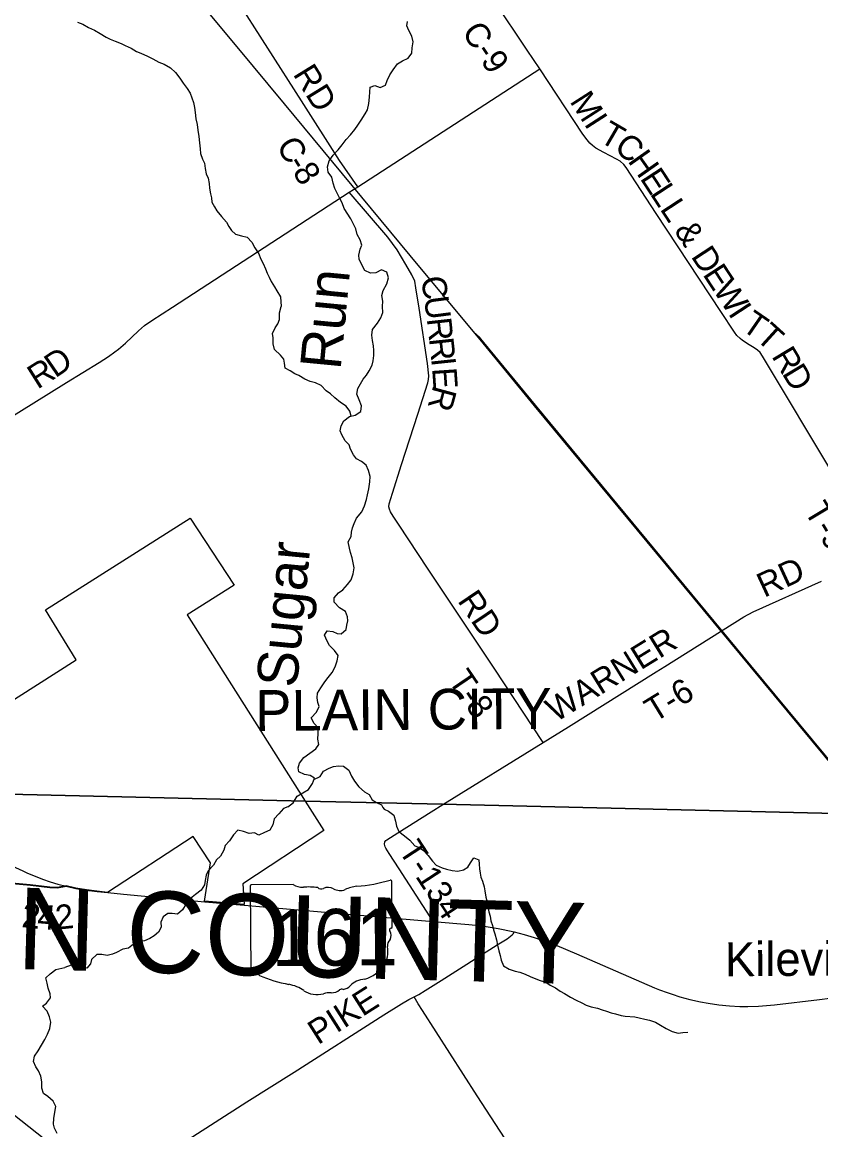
# Model space of a CAD drawing. Extents: x 114843 to 284848, y 317643 to 566895.
# Drawn here: x 135543 to 145352, y 436168 to 449771 of the extents above; entities that cross this region are included whole.
import ezdxf

# ---------------------------------------------------------------- set-up
doc = ezdxf.new("R2010")
doc.units = 0
for name, color, linetype in [('GM_X_Corporation', 7, 'Continuous'), ('GM_X_Corporation_Text', 7, 'Continuous'), ('GM_X_County', 7, 'Continuous'), ('GM_X_County_Road', 7, 'Continuous'), ('GM_X_County_Road_Text', 7, 'Continuous'), ('GM_X_County_Text', 7, 'Continuous'), ('GM_X_Minor_River', 7, 'Continuous'), ('GM_X_Minor_River_Text', 7, 'Continuous'), ('GM_X_Rail_Line', 7, 'Continuous'), ('GM_X_State_Location', 7, 'Continuous'), ('GM_X_State_Route', 7, 'Continuous'), ('GM_X_State_Shield', 7, 'Continuous'), ('GM_X_Township', 7, 'Continuous'), ('GM_X_Township_Road', 7, 'Continuous'), ('GM_X_Township_Road_Text', 7, 'Continuous'), ('GM_X_Unincorporated_Text', 7, 'Continuous')]:
    doc.layers.add(name, color=color, linetype=linetype)

msp = doc.modelspace()

# ---------------------------------------------------------------- linework, layer by layer
at = {"layer": 'GM_X_Corporation'}
msp.add_lwpolyline([(133681, 440330), (136208, 441939), (135832, 442553), (137605, 443679), (138147, 442857), (137568, 442491), (139019, 440206), (139249, 439843), (138253, 439188), (138269, 438934), (137783, 438976), (137857, 439448), (137645, 439771), (136593, 439084), (136462, 439098), (136332, 439114), (136203, 439137), (136085, 439163), (135978, 439145), (135882, 439149), (135643, 439176), (135285, 439209)], dxfattribs=at)
at = {"layer": 'GM_X_County'}
for points in [[(129305, 440437), (129824, 440418), (129960, 440416), (130670, 440400), (130865, 440395), (131182, 440388), (131530, 440380), (131888, 440371), (132489, 440358), (133681, 440330), (133879, 440325), (134855, 440302), (139019, 440206), (140707, 440166), (147260, 440014)], [(147260, 440014), (140707, 440166), (139019, 440206), (134855, 440302), (133879, 440325), (133681, 440330), (132489, 440358), (131888, 440371), (131530, 440380), (131182, 440388), (130865, 440395), (130670, 440400), (129960, 440416), (129824, 440418), (129305, 440437)]]:
    msp.add_lwpolyline(points, dxfattribs=at)
at = {"layer": 'GM_X_County_Road'}
for points in [[(141902, 449196), (141746, 449428), (141342, 450031), (141089, 450411), (140886, 450733), (140854, 450791), (140832, 450838), (140820, 450885), (140819, 450926), (140826, 450962), (140846, 450998), (140894, 451044), (141104, 451178), (141825, 451637), (141918, 451696), (142057, 451782), (142111, 451813), (142494, 451989), (142550, 452014), (142635, 452044), (142710, 452061), (142808, 452078), (145686, 452514)], [(139666, 447749), (139442, 448072), (138972, 448806), (137735, 450748), (137170, 451640), (136941, 451999)], [(134912, 444616), (136089, 445346), (136488, 445593), (136604, 445666), (136683, 445722), (136727, 445754), (136811, 445830), (136973, 445982), (137045, 446044), (137135, 446108), (137388, 446272), (139559, 447682), (139666, 447749), (141902, 449196)], [(134808, 439398), (135097, 439255), (135158, 439230), (135222, 439215), (135287, 439206), (135645, 439173), (135883, 439146), (135979, 439142), (136086, 439160)], [(140358, 437803), (140414, 437832), (140494, 437880), (140688, 438002), (141378, 438441), (141499, 438515), (141562, 438562), (141578, 438581), (141586, 438599)], [(136091, 434943), (136137, 435014), (136225, 435158), (136240, 435179), (136261, 435204), (136287, 435229), (136310, 435248), (136337, 435267), (136393, 435301), (136423, 435314), (136781, 435544), (137584, 436051), (138301, 436511), (138882, 436878), (139987, 437580), (140203, 437715), (140294, 437768), (140358, 437803)], [(146567, 428190), (146545, 428225), (146526, 428251), (146331, 428554), (145936, 429157), (145721, 429491), (145366, 430037), (145064, 430505), (144797, 430918), (144567, 431276), (144032, 432101), (143429, 433037), (143149, 433468), (142166, 434991), (142073, 435132), (141863, 435459), (141131, 436585), (140458, 437632), (140407, 437716), (140358, 437803)]]:
    msp.add_lwpolyline(points, dxfattribs=at)
at = {"layer": 'GM_X_Minor_River'}
for points in [[(136222, 449771), (136289, 449745), (136359, 449703), (136431, 449674), (136500, 449630), (136576, 449588), (136626, 449562), (136686, 449537), (136759, 449509), (136809, 449485), (136881, 449450), (136948, 449412), (137000, 449388), (137082, 449352), (137150, 449319), (137221, 449281), (137289, 449255), (137365, 449210), (137428, 449154), (137478, 449084), (137521, 449020), (137571, 448954), (137608, 448898), (137646, 448784), (137659, 448722), (137669, 448660), (137677, 448584), (137692, 448514), (137702, 448445), (137713, 448367), (137721, 448287), (137728, 448213), (137734, 448159), (137758, 448089), (137783, 448039), (137789, 447975), (137805, 447907), (137826, 447855), (137840, 447789), (137846, 447734), (137857, 447664), (137867, 447612), (137873, 447560), (137906, 447502), (137934, 447452), (137992, 447382), (138055, 447313), (138083, 447261), (138114, 447211), (138164, 447167), (138236, 447145), (138306, 447131), (138363, 447070), (138401, 447000), (138450, 446924), (138470, 446870), (138505, 446806), (138533, 446740), (138551, 446690), (138578, 446640), (138600, 446584), (138644, 446520), (138671, 446470), (138715, 446396), (138723, 446279)], [(139970, 446277), (139974, 446344), (139961, 446413), (139975, 446477), (140021, 446559), (140042, 446630), (140022, 446700), (139956, 446729), (139888, 446691), (139822, 446687), (139753, 446720), (139713, 446792), (139681, 446860), (139678, 446910), (139694, 446981), (139714, 447031), (139695, 447097), (139659, 447165), (139640, 447233), (139610, 447297), (139580, 447355), (139499, 447483), (139474, 447551), (139442, 447615), (139408, 447677), (139385, 447729), (139361, 447795), (139345, 447865), (139302, 447927), (139294, 447995), (139313, 448069), (139361, 448138), (139423, 448202), (139475, 448265), (139524, 448331), (139574, 448387), (139630, 448452), (139664, 448504), (139705, 448567), (139757, 448643), (139783, 448695), (139801, 448772), (139808, 448850), (139814, 448914), (139816, 448974), (139876, 448991), (139940, 448967), (140006, 448997), (140025, 449054), (140057, 449122), (140101, 449186), (140151, 449257), (140215, 449297), (140283, 449328), (140328, 449388), (140334, 449456), (140344, 449528), (140327, 449600), (140291, 449670), (140266, 449724), (140274, 449779)], [(139585, 444932), (139567, 444994), (139521, 445056), (139454, 445102), (139384, 445159), (139331, 445207), (139279, 445244), (139214, 445310), (139148, 445343), (139080, 445357), (139013, 445386), (138941, 445432), (138891, 445452), (138836, 445487), (138772, 445521), (138765, 445583), (138757, 445633), (138716, 445683), (138644, 445750), (138625, 445822), (138625, 445894), (138616, 445947), (138650, 446015), (138683, 446067), (138705, 446120), (138705, 446200), (138723, 446279)], [(139848, 445863), (139837, 445928), (139847, 445998), (139908, 446073), (139949, 446141), (139971, 446204), (139970, 446277)], [(138807, 440133), (138870, 440182), (138922, 440266), (138992, 440307), (139059, 440346), (139109, 440420), (139132, 440487), (139082, 440520), (139012, 440532), (138941, 440565), (138933, 440615), (138950, 440670), (139004, 440740), (139075, 440795), (139151, 440848), (139185, 440900), (139174, 440966), (139177, 441037), (139179, 441105), (139128, 441159), (139092, 441228), (139157, 441297), (139189, 441366), (139176, 441416), (139166, 441472), (139169, 441530), (139211, 441597), (139262, 441669), (139302, 441722), (139349, 441785), (139388, 441853), (139414, 441926), (139423, 441992), (139379, 442054), (139318, 442117), (139288, 442169), (139255, 442241), (139290, 442298), (139359, 442288), (139411, 442265), (139461, 442259), (139523, 442314), (139532, 442366), (139542, 442420), (139539, 442470), (139513, 442534), (139440, 442578), (139374, 442647), (139377, 442702), (139427, 442764), (139482, 442801), (139540, 442864), (139583, 442924), (139609, 442995), (139620, 443071), (139609, 443131), (139595, 443191), (139576, 443259), (139562, 443311), (139547, 443391), (139585, 443456), (139590, 443506), (139602, 443562), (139619, 443615), (139649, 443681), (139714, 443758), (139749, 443830), (139773, 443909), (139784, 443967), (139802, 444039), (139815, 444124), (139818, 444192), (139798, 444266), (139769, 444332), (139711, 444374), (139648, 444409), (139612, 444459), (139577, 444525), (139559, 444581), (139512, 444631), (139468, 444702), (139449, 444752), (139461, 444813), (139494, 444873), (139564, 444928), (139634, 444943), (139703, 444989), (139711, 445058), (139684, 445132), (139653, 445204), (139665, 445270), (139698, 445330), (139732, 445385), (139771, 445437), (139805, 445490), (139842, 445558), (139856, 445613), (139863, 445679), (139863, 445739), (139858, 445797), (139848, 445863)], [(139127, 440471), (139204, 440507), (139246, 440572), (139315, 440611), (139365, 440631), (139429, 440638), (139491, 440636), (139556, 440585), (139588, 440513), (139625, 440449), (139678, 440379), (139746, 440318), (139806, 440288), (139843, 440222), (139897, 440187), (139956, 440159), (139972, 440126), (139988, 440105)], [(138807, 440133), (138754, 440113), (138694, 440048), (138640, 439986), (138624, 439914), (138587, 439847), (138519, 439819), (138451, 439786), (138398, 439816), (138332, 439806), (138262, 439832), (138192, 439850), (138138, 439791), (138091, 439719), (138035, 439662), (138021, 439604), (137981, 439530), (137931, 439485), (137893, 439419), (137826, 439347), (137804, 439296), (137792, 439232), (137784, 439178), (137743, 439112), (137673, 439059), (137609, 439011), (137557, 438944), (137511, 438872), (137453, 438818), (137387, 438827), (137331, 438823), (137275, 438785), (137248, 438720), (137252, 438658), (137216, 438594), (137166, 438552), (137110, 438517), (137044, 438491), (136978, 438479), (136912, 438448), (136850, 438400), (136778, 438386), (136704, 438345), (136652, 438327), (136588, 438311), (136524, 438322), (136460, 438322), (136396, 438260), (136381, 438205), (136339, 438153), (136287, 438159), (136216, 438185), (136146, 438190), (136069, 438161)], [(139988, 440105), (140041, 440082), (140107, 440034), (140130, 439960), (140140, 439896), (140170, 439832), (140239, 439780), (140305, 439724), (140365, 439656), (140419, 439636), (140474, 439600), (140530, 439536), (140584, 439468), (140628, 439418), (140703, 439384), (140755, 439368), (140823, 439353), (140895, 439345), (140965, 439361), (141015, 439396), (141051, 439446), (141089, 439508), (141153, 439486), (141157, 439430), (141161, 439372), (141167, 439322), (141178, 439272), (141198, 439220), (141218, 439154), (141226, 439103), (141239, 439025), (141253, 438967), (141261, 438911), (141273, 438845), (141290, 438793), (141300, 438733), (141318, 438677), (141330, 438626), (141349, 438574), (141367, 438502), (141381, 438436), (141397, 438366), (141412, 438310), (141428, 438250), (141454, 438182), (141524, 438140), (141597, 438118), (141655, 438106), (141721, 438078), (141781, 438052), (141833, 438029), (141903, 438001), (141974, 437981), (142028, 437945), (142094, 437911), (142150, 437873), (142202, 437842), (142279, 437796), (142347, 437760), (142417, 437726), (142469, 437698), (142533, 437678), (142611, 437663), (142666, 437643), (142718, 437625), (142776, 437607), (142830, 437591), (142900, 437573), (142950, 437566), (143066, 437558), (143122, 437542), (143191, 437528), (143249, 437517), (143321, 437491), (143383, 437453), (143453, 437411), (143526, 437375), (143598, 437356), (143656, 437362), (143718, 437366)], [(135972, 436122), (135942, 436188), (135930, 436240), (135932, 436308), (135945, 436384), (135959, 436454), (135925, 436521), (135857, 436577), (135805, 436615), (135784, 436682), (135786, 436758), (135772, 436828), (135746, 436892), (135712, 436944), (135681, 437007), (135697, 437073), (135741, 437139), (135782, 437209), (135822, 437277), (135856, 437345), (135883, 437413), (135897, 437489), (135879, 437555), (135850, 437624), (135792, 437686), (135844, 437722), (135890, 437788), (135886, 437838), (135865, 437908), (135851, 437968), (135835, 438033), (135889, 438085), (135958, 438138), (136069, 438161)]]:
    msp.add_lwpolyline(points, dxfattribs=at)
at = {"layer": 'GM_X_Rail_Line'}
for points in [[(145998, 440038), (144484, 441862), (141837, 445060), (141203, 445828), (140307, 446907), (138764, 448766), (138183, 449466), (136987, 450906)], [(146007, 440046), (144493, 441870), (141847, 445068), (141213, 445836), (141158, 445902), (141088, 445966)], [(128479, 440489), (130998, 439418), (131780, 439073), (132352, 438743), (133270, 438069), (136074, 435852), (137429, 434713), (140276, 432132), (143769, 428946), (146519, 426434), (147203, 425812)]]:
    msp.add_lwpolyline(points, dxfattribs=at)
at = {"layer": 'GM_X_State_Route'}
msp.add_line((137788, 438969), (138270, 438927), dxfattribs=at)
for points in [[(133954, 439777), (134265, 439747), (134476, 439725), (134541, 439716), (134638, 439700), (134702, 439687), (134766, 439671), (134861, 439645), (134923, 439626), (135016, 439593), (135107, 439556), (135373, 439432), (135552, 439347), (135611, 439320), (135702, 439282), (135794, 439247), (135887, 439215), (135981, 439187), (136086, 439160)], [(136086, 439160), (136204, 439134), (136333, 439111), (136464, 439095), (136594, 439081)], [(136594, 439081), (136790, 439061), (137788, 438969)], [(138270, 438927), (140593, 438728), (141031, 438690), (141194, 438672), (141291, 438658), (141388, 438641), (141452, 438629), (141586, 438599), (141707, 438568), (141832, 438531), (141957, 438490), (142108, 438434), (142351, 438331), (143311, 437914), (143372, 437889), (143464, 437855), (143525, 437833), (143619, 437803), (143745, 437769), (143872, 437740), (143969, 437722), (144098, 437703), (144229, 437691), (144359, 437684), (144457, 437683), (144588, 437688), (144686, 437695), (144783, 437704), (145334, 437767), (145464, 437784)]]:
    msp.add_lwpolyline(points, dxfattribs=at)
at = {"layer": 'GM_X_State_Shield'}
for p, q in [((138345, 439159), (138352, 438103)), ((138871, 439181), (138362, 439178)), ((140089, 438664), (140085, 439216)), ((140089, 438664), (140089, 438664))]:
    msp.add_line(p, q, dxfattribs=at)
for centre, major_axis, ratio, start_param, end_param in [((139455, 440626), (1845, 13), 0.800001, 4.814396, 5.042371), ((140065, 439218), (19.4, 0.1), 0.8, 6.141152, 7.989035), ((138365, 439162), (20.2, 0.1), 0.8, 1.712693, 3.28349), ((138992, 439305), (196, 1), 0.8, 4.042523, 4.731795), ((139062, 438589), (702, 5), 0.8, 1.404758, 1.657858), ((139217, 439173), (56.4, 0.4), 0.8, 3.836095, 5.185415), ((139301, 439052), (117, 1), 0.8, 0.950623, 2.079405), ((139451, 439220), (141, 1), 0.8, 4.081561, 5.145723), ((139703, 438865), (371, 3), 0.8, 1.699011, 2.107814), ((140084, 438623), (30, 0.2), 0.8, 1.883978, 3.671073), ((139894, 438552), (180, 1), 0.8, 5.934695, 6.695948), ((140068, 438661), (20.7, 0.1), 0.8, 5.05454, 6.418171), ((139574, 438358), (462, 3), 0.8, 5.101753, 6.440018), ((140160, 438433), (131, 1), 0.8, 2.387724, 3.262537), ((138373, 438101), (20.3, 0.1), 0.8, 3.00124, 4.508301), ((138375, 438209), (155, 1), 0.8, 4.665946, 4.897461), ((138408, 438042), (56, 0.4), 0.8, 0.519207, 1.627899), ((139108, 438997), (1333, 10), 0.800001, 4.195996, 4.488959), ((139773, 437816), (253, 2), 0.8, 1.647645, 2.488433), ((138720, 437631), (417, 3), 0.8, 0.823519, 1.323588), ((139168, 438042), (265, 2), 0.8, 4.026481, 4.996735), ((139341, 437965), (141, 1), 0.8, 4.691044, 5.507374), ((139469, 437863), (39.7, 0.3), 0.8, 1.147584, 2.315152), ((139451, 438008), (149, 1), 0.8, 4.937069, 5.64225), ((139324, 437678), (217, 2), 0.8, 1.495662, 1.94098)]:
    msp.add_ellipse(centre, major_axis=major_axis, ratio=ratio, start_param=start_param, end_param=end_param, dxfattribs=at)
at = {"layer": 'GM_X_Township'}
for points in [[(147260, 440014), (140707, 440166), (139019, 440206), (134855, 440302), (133879, 440325), (133681, 440330), (132489, 440358), (131888, 440371), (131530, 440380), (131182, 440388), (130865, 440395), (130670, 440400), (129960, 440416), (129824, 440418), (129305, 440437)], [(129305, 440437), (129824, 440418), (129960, 440416), (130670, 440400), (130865, 440395), (131182, 440388), (131530, 440380), (131888, 440371), (132489, 440358), (133681, 440330), (133879, 440325), (134855, 440302), (139019, 440206), (140707, 440166), (147260, 440014)]]:
    msp.add_lwpolyline(points, dxfattribs=at)
at = {"layer": 'GM_X_Township_Road'}
msp.add_line((142254, 441119), (143328, 441792), dxfattribs=at)
for points in [[(146091, 443242), (145524, 444186), (144634, 445668), (144605, 445714), (144574, 445744), (144535, 445772), (144471, 445810), (144389, 445862), (144361, 445884), (144322, 445923), (144291, 445965), (144125, 446218), (143331, 447419), (142960, 447984), (142931, 448022), (142886, 448063), (142843, 448090), (142687, 448170), (142589, 448225), (142546, 448256), (142514, 448285), (142481, 448325), (142431, 448397), (141902, 449196)], [(141941, 440923), (141340, 441836), (140531, 443055), (140166, 443604), (140100, 443705), (140068, 443757), (140053, 443789), (140047, 443817), (140050, 443854), (140090, 443988), (140204, 444338), (140401, 444956), (140525, 445340), (140534, 445384), (140537, 445428), (140520, 445579), (140418, 446259), (140380, 446508), (140364, 446590), (140331, 446666), (140257, 446796), (140148, 446975), (140033, 447129), (139559, 447682)], [(143328, 441792), (143435, 441859), (144405, 442466), (144522, 442530), (145359, 442907)], [(140709, 440164), (141941, 440923), (142254, 441119)], [(140593, 438728), (140174, 439373), (140049, 439562), (140009, 439629), (140001, 439645), (139992, 439676), (139999, 439707), (140011, 439721), (140022, 439730), (140156, 439814), (140567, 440072), (140709, 440164)]]:
    msp.add_lwpolyline(points, dxfattribs=at)

# ---------------------------------------------------------------- texts
at = {"layer": 'GM_X_Corporation_Text'}
msp.add_text('PLAIN CITY', height=500, rotation=0.4116, dxfattribs=at).set_placement((138407, 441067))
at = {"layer": 'GM_X_County_Road_Text'}
for s, rotation, p in [('C-9', 303.3399, (140935, 449652)), ('RD', 301.6282, (138863, 449133)), ('C', 301.5754, (138657, 448251)), ('-', 301.8633, (138787, 448039)), ('8', 303.3195, (138856, 447928)), ('D', 34.5195, (135951, 445394)), ('R', 32.222, (135732, 445256)), ('2', 354.1215, (135530, 438659)), ('4', 355.2629, (135721, 438639)), ('2', 6.0827, (135967, 438625)), ('PIKE', 32.3844, (139177, 437207))]:
    msp.add_text(s, height=300, rotation=rotation, dxfattribs=at).set_placement(p)
at = {"layer": 'GM_X_County_Text'}
msp.add_text('MADISON COUNTY', height=1000.03, rotation=358.4409, dxfattribs=at).set_placement((130198, 438288))
at = {"layer": 'GM_X_Minor_River_Text'}
for s, rotation, p in [('Run', 84.5268, (139453, 445492)), ('Sugar', 84.5266, (138916, 441588))]:
    msp.add_text(s, height=500, rotation=rotation, dxfattribs=at).set_placement(p)
at = {"layer": 'GM_X_State_Location'}
for s, p in [('s', (139200, 438567)), ('r', (139200, 438567)), ('161', (138847, 438492))]:
    msp.add_text(s, height=1, rotation=0.4116, dxfattribs=at).set_placement(p)
at = {"layer": 'GM_X_State_Shield'}
msp.add_text('161', height=696.1, rotation=0.4116, dxfattribs=at).set_placement((138608, 438179))
at = {"layer": 'GM_X_Township_Road_Text'}
for s, rotation, p in [('M', 302.6541, (142261, 448798)), ('I', 302.7762, (142437, 448523)), ('T', 329.8159, (142615, 448314)), ('C', 320.0919, (142798, 448209)), ('H', 305.196, (142973, 448066)), ('E', 303.2293, (143124, 447852)), ('L', 303.1853, (143246, 447665)), ('L', 303.1794, (143369, 447477)), ('&', 303.1831, (143543, 447212)), ('D', 303.1844, (143750, 446895)), ('E', 303.1839, (143894, 446674)), ('C', 278.5848, (140441, 446632)), ('W', 303.1802, (144017, 446486)), ('U', 277.3753, (140478, 446390)), ('I', 303.108, (144207, 446195)), ('T', 325.4445, (144363, 446001)), ('R', 276.2803, (140512, 446129)), ('T', 317.7549, (144540, 445881)), ('R', 276.1506, (140539, 445885)), ('R', 301.1486, (144740, 445669)), ('I', 276.0725, (140565, 445640)), ('E', 273.9452, (140578, 445520)), ('D', 301.0613, (144868, 445458)), ('R', 254.9203, (140596, 445322)), ('T-9', 301.0483, (145142, 443769)), ('RD', 24.7746, (144656, 442700)), ('RD', 303.8294, (140883, 442665)), ('WARNER', 31.5938, (142096, 441167)), ('T-8', 304.2331, (140768, 441689)), ('T-6', 31.4572, (143308, 441164)), ('T-134', 303.1245, (140158, 439600))]:
    msp.add_text(s, height=300, rotation=rotation, dxfattribs=at).set_placement(p)
at = {"layer": 'GM_X_Unincorporated_Text'}
msp.add_text('Kileville', height=417, rotation=0.4118, dxfattribs=at).set_placement((144175, 438053))

doc.saveas('drawing.dxf')
